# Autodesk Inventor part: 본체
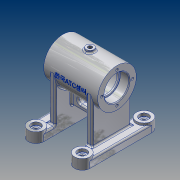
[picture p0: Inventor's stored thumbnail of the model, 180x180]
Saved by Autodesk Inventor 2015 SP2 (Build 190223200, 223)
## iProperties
Created: 2015-11
Part Number: 본체
Material: 알루미늄 6061
Document SubType Name: Modeling
Designer: AMC
Density: 2.7 g/cm^3
Appearance: 알루미늄 - 평지
Author: AMC
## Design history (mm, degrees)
sketch "스케치1"
  geometry: C1 r 25 at (0, 0); 1 further point
  constraints: 1 centre point, 1 coincident
  dimensions: "d0" = 50 diameter of C1
extrude "돌출1" new body sketch "스케치1" stored distance "d1" = 70; taper "d2" = 0 deg
node "작업 평면2"
sketch "스케치2" dims "d14" = 20, "d17" = 20
  geometry: L1 (-40, -40)-(40, -40); L2 (40, -40)-(40, 40); L3 (40, 40)-(-40, 40); L4 (-40, 40)-(-40, -40); L5 (-40, -40)-(40, 40); L6 (40, -40)-(-40, 40); L7 (-20, 40)-(20, 40); L8 (20, 40)-(20, -40); L9 (20, -40)-(-20, -40); L10 (-20, -40)-(-20, 40); C1 r 10 at (30, 40); C2 r 10 at (-30, -40); 3 further points
  constraints: 20 end point, 6 point on line, 4 parallel, 2 centre point, 2 horizontal, 2 horizontal alignment, 2 midpoint, 2 perpendicular, 4 other
  dimensions: "d4" = 80 distance of L3.end L2.end; "d5" = 80 distance of L2.end L1.end; "d15" = 20 diameter of C1; "d16" = 20 diameter of C2; "d18" = 10 distance from line of L4 point (-30, 40); "d19" = 10 distance from line of L2 C1.centre; "d20" = 10 distance from line of point (30, -40) L2; "d21" = 10 distance from line of L4 C2.centre
extrude "돌출2" join sketch "스케치2" distance "d22" = 10; taper "d23" = 0 deg
extrude "돌출3" join sketch "스케치2" distance "d24" = 13; taper "d25" = 0 deg
sketch "스케치6"
  geometry: L1 (20, -68)-(20, -58) reference; L2 (40, -68)-(20, -68) reference; L3 (40, -68)-(40, -58) reference; L4 (20, -58)-(40, -58) reference; L5 (40, -55)-(20, -55) reference; L6 (-40, -68)-(-40, -58) reference; L7 (-20, -68)-(-40, -68) reference; L8 (-20, -68)-(-20, -58) reference; L9 (-40, -58)-(-20, -58) reference; L10 (-20, -55)-(-40, -55) reference; L11 (20, -68)-(28, -68); L12 (28, -68)-(28, 0); L13 (28, 0)-(20, 0); L14 (20, 0)-(20, -68); L15 (-20, -68)-(-28, -68); L16 (-28, -68)-(-28, 0); L17 (-28, 0)-(-20, 0); L18 (-20, 0)-(-20, -68); L19 (35, -25)-(35, 25) reference; L20 (-35, 25)-(-35, -25) reference; L21 (-20, -25)-(-20, -45); L22 (-20, -45)-(20, -45); L23 (20, -45)-(20, -25); L24 (20, -35)-(-20, -35); L25 (8, -35)-(-8, -35); L26 (8, -31.5)-(-8, -31.5); L27 (-8, -38.5)-(8, -38.5); L28 (20, -19)-(-20, -19); L29 (0, -19)-(0, -45); A1 r 3.5 centre (8, -35) between (8, -38.5) and (8, -31.5); A2 r 3.5 centre (-8, -35) between (-8, -31.5) and (-8, -38.5); 3 further points
  constraints: 36 end point, 6 midpoint, 6 parallel, 6 point on line, 4 point on circle, 4 tangent, 3 perpendicular, 2 centre point, 2 horizontal, 1 coincident
  dimensions: "d26" = 8 distance between parallel lines of L12 L14; "d27" = 8 distance between parallel lines of L16 L18; "d28" = 68 distance between parallel lines of L2 L13; "d29" = 68 distance between parallel lines of L15 L17; "d32" = 7 diameter of A2; "d33" = 33 distance between parallel lines of L7 L25; "d39" = 26 distance between parallel lines of L22 L28; "d40" = 10 distance between parallel lines of L22 L24; "d108" = 23 dimension on A2 A1
  node "투영된 루프1"
  node "투영된 루프2"
  node "투영된 루프3"
extrude "돌출4" join sketch "스케치6" stored distance "d34" = 50; taper "d35" = 0 deg
extrude "돌출5" join sketch "스케치6" stored distance "d36" = 8; taper "d37" = 0 deg
hole "구멍1" diameter "d43" = 6; stored, may be unused: countersink angle "d47" = 90 deg, drill point angle "d49" = 118 deg; dims "d41" = 10, "d42" = 10, "d44" = 6, "d45" = 12, "d46" = 4, "d48" = 8
fillet "모깎기1" dims "d50" = 0.3
fillet "모깎기2" dims "d51" = 0.3
chamfer "모따기1" distance "d52" = 1; stored, may be unused: second distance "d53" = 2, angle "d54" = 45 deg
sketch "스케치7"
  geometry: C1 r 5 at (0, 0); 1 further point
  constraints: 1 centre point, 1 coincident
  dimensions: "d100" = 10 diameter of C1
extrude "돌출6" join sketch "스케치7" distance "d101" = 28; taper "d102" = 0 deg
hole "구멍2" diameter "d57" = 32; stored, may be unused: countersink angle "d61" = 90 deg, drill point angle "d63" = 0 deg; dims "d55" = 10, "d56" = 10, "d58" = 6, "d59" = 12, "d60" = 4, "d62" = 12
hole "구멍3" diameter "d66" = 28; stored, may be unused: countersink angle "d70" = 90 deg, drill point angle "d72" = 0 deg; dims "d64" = 10, "d65" = 10, "d67" = 6, "d68" = 12, "d69" = 4, "d71" = 2
hole "구멍5" diameter "d84" = 32; stored, may be unused: countersink angle "d88" = 90 deg, drill point angle "d90" = 0 deg; dims "d82" = 10, "d83" = 10, "d85" = 6, "d86" = 12, "d87" = 4, "d89" = 12
sketch "스케치8"
  geometry: L1 (0, 0)-(12.5, -21.651); L2 (0, 0)-(25, 0); C1 r 16 at (0, 0) reference; A1 r 25 centre (0, 0) between (12.5, -21.651) and (25, 0) reference; 2 further points
  constraints: 4 end point, 2 point on circle, 1 coincident, 1 horizontal
  dimensions: "d103" = 60 deg angle of L1 L2
  node "투영된 루프4"
node "작업 평면6"
  node "작업 평면5"
sketch "스케치9"
  geometry: C1 r 6 at (0, 0); 1 further point
  constraints: 1 centre point, 1 coincident
  dimensions: "d105" = 12 diameter of C1
extrude "돌출7" join sketch "스케치9" distance "d106" = 28; taper "d107" = 0 deg
hole "구멍4" diameter "d75" = 40; stored, may be unused: countersink angle "d79" = 90 deg, drill point angle "d81" = 0 deg; dims "d73" = 10, "d74" = 10, "d76" = 6, "d77" = 12, "d78" = 4, "d80" = 42
hole "구멍6" diameter "d93" = 28; stored, may be unused: countersink angle "d97" = 90 deg, drill point angle "d99" = 0 deg; dims "d91" = 10, "d92" = 10, "d94" = 6, "d95" = 12, "d96" = 4, "d98" = 2
fillet "모깎기3" dims "d109" = 2
fillet "모깎기4" dims "d110" = 2
fillet "모깎기5" dims "d111" = 2
fillet "모깎기6" dims "d112" = 2
fillet "모깎기7" dims "d113" = 2
hole "구멍7" diameter "d116" = 5.188; stored, may be unused: countersink angle "d120" = 90 deg, drill point angle "d122" = 0 deg; dims "d114" = 10, "d115" = 10, "d117" = 12, "d118" = 12, "d119" = 4, "d121" = 16
hole "구멍8" diameter "d125" = 5.188; stored, may be unused: countersink angle "d129" = 90 deg, drill point angle "d131" = 0 deg; dims "d123" = 10, "d124" = 10, "d126" = 12, "d127" = 12, "d128" = 4, "d130" = 16
sketch "스케치10" dims "d132" = 40
  geometry: C1 r 16 at (0, 0) reference; C2 r 25 at (0, 0) reference; 3 further points
  constraints: 2 vertical alignment, 1 coincident, 2 other
hole "구멍9" sketch "스케치10" at (0, 20) diameter "d133" = 3.242; stored, may be unused: countersink angle "d137" = 90 deg, drill point angle "d139" = 0 deg; dims "d134" = 8, "d135" = 12, "d136" = 4, "d138" = 10
node "작업 평면7"
sketch "스케치12"
  geometry: L1 (-22.5, 3.5)-(22.5, 3.5); L2 (22.5, 3.5)-(22.5, -3.5); L3 (22.5, -3.5)-(-22.5, -3.5); L4 (-22.5, -3.5)-(-22.5, 3.5); L5 (-22.5, 0)-(22.5, 0); L6 (0, 3.5)-(0, -3.5); L7 (-35, 25)-(-35, -25) reference; 3 further points
  constraints: 6 midpoint, 4 end point, 1 coincident, 1 horizontal, 2 other
  dimensions: "d144" = 45 distance between parallel lines of L2 L4; "d145" = 7 distance between parallel lines of L3 L1; "d146" = 0 distance of point (0, 0) point (0, 0); "d148" = 35 distance between parallel lines of L6 L7
feature "엠보싱1" sketch "스케치12" dims "d22" = 10, "d149" = 0.5, "d150" = 0
fillet "모깎기8" dims "d151" = 3
fillet "모깎기9" dims "d152" = 0.3
chamfer "모따기2" distance "d153" = 1; stored, may be unused: second distance "d154" = 2, angle "d155" = 45 deg
node "솔리드1"
mirror "대칭1"
mirror "대칭2"
pattern_circular "원형 패턴1" dims angle "d141" = 360 deg
mirror "대칭3"
node "작업 평면3"
node "작업 평면4"
node "투영된 루프5"
other parameters: "d3" = -68, "d104" = -25, "d143" = 0
